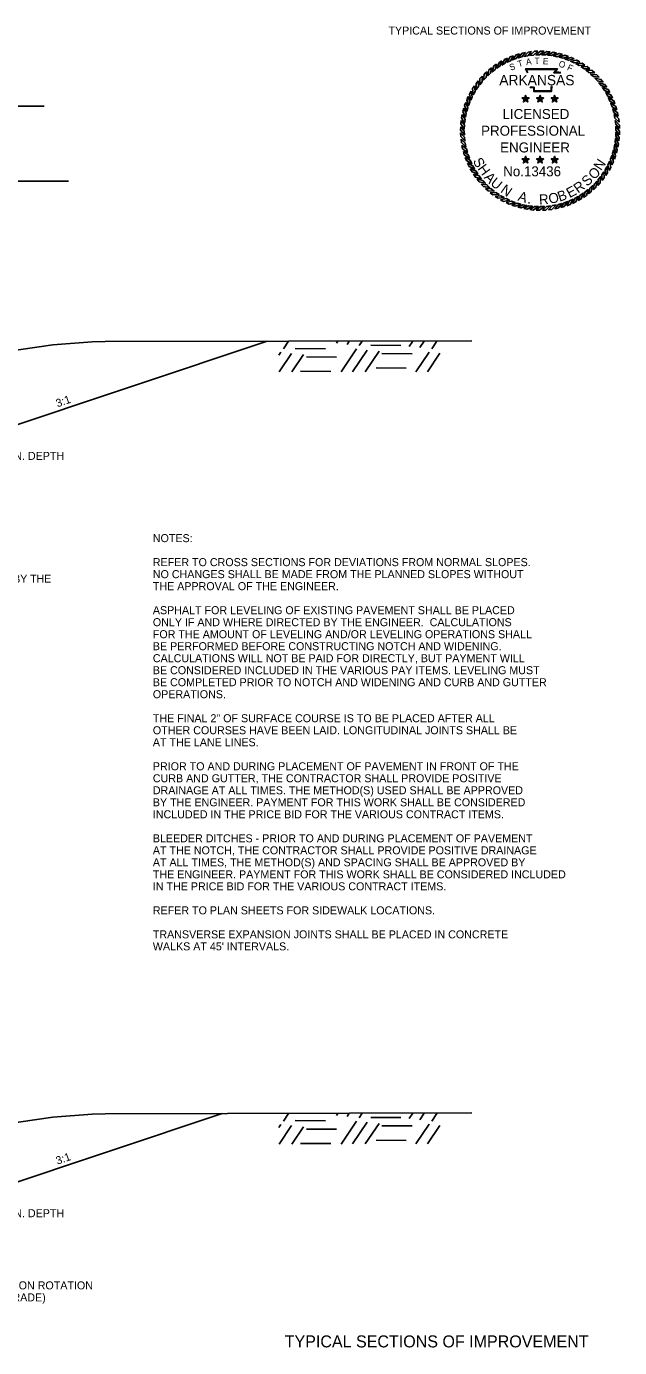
# Model space of a CAD drawing. Extents: x 1001270 to 1003428, y 1840152 to 1842912.
# Drawn here: x 1001384 to 1001428.5, y 1842241.3 to 1842340.4 of the extents above; entities that cross this region are included whole.
import ezdxf

# ---------------------------------------------------------------- set-up
doc = ezdxf.new("R2010")
doc.units = 0
for name, color, linetype in [('1', 7, 'Continuous'), ('19', 7, 'Continuous'), ('60', 7, 'Continuous'), ('Default', 7, 'Continuous'), ('G-ANNO-SYMB', 7, 'Continuous')]:
    doc.layers.add(name, color=color, linetype=linetype)

msp = doc.modelspace()

# ---------------------------------------------------------------- linework, layer by layer
at = {"layer": '19'}
for p, q in [((1001364.368, 1842334.379), (1001385.294, 1842334.379)), ((1001364.368, 1842328.779), (1001387.13, 1842328.779)), ((1001379.87, 1842309.383), (1001402.036, 1842316.771)), ((1001403.257, 1842316.192), (1001403.648, 1842316.775)), ((1001407.242, 1842316.626), (1001407.348, 1842316.776)), ((1001408.037, 1842316.534), (1001408.203, 1842316.779)), ((1001408.932, 1842316.442), (1001409.158, 1842316.781)), ((1001412.696, 1842316.387), (1001412.958, 1842316.782)), ((1001413.491, 1842316.295), (1001413.823, 1842316.783)), ((1001414.386, 1842316.203), (1001414.767, 1842316.777)), ((1001402.917, 1842315.724), (1001403.071, 1842315.95)), ((1001402.939, 1842314.475), (1001403.866, 1842315.858)), ((1001403.894, 1842314.478), (1001404.761, 1842315.766)), ((1001404.145, 1842316.231), (1001406.405, 1842316.21)), ((1001407.594, 1842314.479), (1001408.746, 1842316.2)), ((1001408.449, 1842314.481), (1001409.541, 1842316.108)), ((1001409.404, 1842314.484), (1001410.436, 1842316.016)), ((1001409.82, 1842316.471), (1001412.08, 1842316.46)), ((1001410.65, 1842315.843), (1001412.92, 1842315.831)), ((1001413.204, 1842314.485), (1001414.2, 1842315.96)), ((1001414.059, 1842314.487), (1001414.995, 1842315.869)), ((1001404.985, 1842315.602), (1001407.245, 1842315.58)), ((1001410.208, 1842314.773), (1001412.467, 1842314.751)), ((1001404.532, 1842314.523), (1001406.803, 1842314.51)), ((1001379.87, 1842252.613), (1001398.674, 1842258.881)), ((1001403.257, 1842258.309), (1001403.648, 1842258.892)), ((1001404.145, 1842258.348), (1001406.405, 1842258.327)), ((1001407.242, 1842258.743), (1001407.348, 1842258.893)), ((1001407.594, 1842256.596), (1001408.746, 1842258.317)), ((1001408.037, 1842258.651), (1001408.203, 1842258.896)), ((1001408.449, 1842256.598), (1001409.541, 1842258.225)), ((1001408.932, 1842258.559), (1001409.158, 1842258.898)), ((1001409.82, 1842258.589), (1001412.08, 1842258.577)), ((1001412.696, 1842258.504), (1001412.958, 1842258.899)), ((1001413.491, 1842258.412), (1001413.823, 1842258.9)), ((1001414.386, 1842258.32), (1001414.767, 1842258.894)), ((1001402.917, 1842257.841), (1001403.071, 1842258.067)), ((1001402.939, 1842256.592), (1001403.866, 1842257.975)), ((1001403.894, 1842256.595), (1001404.761, 1842257.883)), ((1001404.985, 1842257.719), (1001407.245, 1842257.697)), ((1001409.404, 1842256.601), (1001410.436, 1842258.133)), ((1001410.65, 1842257.96), (1001412.92, 1842257.948)), ((1001413.204, 1842256.602), (1001414.2, 1842258.077)), ((1001414.059, 1842256.604), (1001414.995, 1842257.986)), ((1001404.532, 1842256.64), (1001406.803, 1842256.627)), ((1001410.208, 1842256.89), (1001412.467, 1842256.868))]:
    msp.add_line(p, q, dxfattribs=at)
for points in [[(1001308.144, 1842305.359), (1001317.69, 1842306.018), (1001325.322, 1842307.545), (1001329.477, 1842307.756), (1001334.361, 1842308.581), (1001340.15, 1842308.799), (1001346.517, 1842309.325), (1001351.216, 1842309.645), (1001358.361, 1842310.429), (1001362.7, 1842310.493), (1001370.347, 1842310.619), (1001372.903, 1842311.251), (1001376.995, 1842314.166), (1001381.307, 1842315.815), (1001385.954, 1842316.502), (1001388.908, 1842316.716)], [(1001388.908, 1842316.716), (1001389.885, 1842316.745), (1001417.402, 1842316.805)], [(1001308.144, 1842247.476), (1001317.69, 1842248.135), (1001325.322, 1842249.662), (1001329.477, 1842249.873), (1001334.361, 1842250.698), (1001340.15, 1842250.916), (1001346.517, 1842251.442), (1001351.216, 1842251.762), (1001358.361, 1842252.546), (1001362.7, 1842252.61), (1001370.347, 1842252.736), (1001372.903, 1842253.368), (1001376.995, 1842256.283), (1001381.307, 1842257.932), (1001385.954, 1842258.619), (1001388.908, 1842258.834)], [(1001388.908, 1842258.834), (1001389.885, 1842258.862), (1001417.402, 1842258.922)]]:
    msp.add_lwpolyline(points, dxfattribs=at)
at = {"layer": 'G-ANNO-SYMB'}
for points in [[(1001421.88, 1842338.481), (1001421.625, 1842338.448), (1001421.314, 1842338.114), (1001421.586, 1842338.166)], [(1001422.347, 1842338.513), (1001422.091, 1842338.5), (1001421.754, 1842338.191), (1001422.029, 1842338.221)], [(1001422.816, 1842338.508), (1001422.559, 1842338.515), (1001422.199, 1842338.233), (1001422.476, 1842338.242)], [(1001423.282, 1842338.466), (1001423.027, 1842338.493), (1001422.646, 1842338.241), (1001422.923, 1842338.228)], [(1001423.744, 1842338.388), (1001423.492, 1842338.435), (1001423.092, 1842338.213), (1001423.367, 1842338.179)], [(1001419.256, 1842337.545), (1001419.045, 1842337.4), (1001418.919, 1842336.96), (1001419.138, 1842337.13)], [(1001419.658, 1842337.785), (1001419.436, 1842337.657), (1001419.276, 1842337.229), (1001419.507, 1842337.381)], [(1001420.078, 1842337.993), (1001419.846, 1842337.884), (1001419.653, 1842337.469), (1001419.896, 1842337.603)], [(1001420.513, 1842338.168), (1001420.273, 1842338.077), (1001420.048, 1842337.679), (1001420.3, 1842337.793)], [(1001420.96, 1842338.308), (1001420.714, 1842338.236), (1001420.458, 1842337.857), (1001420.719, 1842337.951)], [(1001421.416, 1842338.413), (1001421.165, 1842338.36), (1001420.881, 1842338.002), (1001421.148, 1842338.075)], [(1001424.198, 1842338.273), (1001423.951, 1842338.34), (1001423.535, 1842338.151), (1001423.806, 1842338.095)], [(1001424.642, 1842338.124), (1001424.401, 1842338.21), (1001423.971, 1842338.054), (1001424.237, 1842337.976)], [(1001425.073, 1842337.94), (1001424.839, 1842338.045), (1001424.398, 1842337.923), (1001424.658, 1842337.825)], [(1001425.488, 1842337.723), (1001425.263, 1842337.846), (1001424.814, 1842337.759), (1001425.065, 1842337.641)], [(1001425.885, 1842337.474), (1001425.67, 1842337.614), (1001425.216, 1842337.562), (1001425.457, 1842337.425)], [(1001418.18, 1842336.645), (1001418.008, 1842336.455), (1001417.988, 1842335.998), (1001418.161, 1842336.215)], [(1001418.515, 1842336.973), (1001418.329, 1842336.797), (1001418.273, 1842336.343), (1001418.462, 1842336.545)], [(1001418.874, 1842337.273), (1001418.675, 1842337.112), (1001418.584, 1842336.664), (1001418.789, 1842336.851)], [(1001426.261, 1842337.195), (1001426.058, 1842337.351), (1001425.601, 1842337.335), (1001425.83, 1842337.179)], [(1001426.614, 1842336.887), (1001426.424, 1842337.059), (1001425.967, 1842337.079), (1001426.183, 1842336.905)], [(1001426.942, 1842336.552), (1001426.765, 1842336.738), (1001426.312, 1842336.794), (1001426.514, 1842336.604)], [(1001427.242, 1842336.192), (1001427.081, 1842336.392), (1001426.633, 1842336.483), (1001426.82, 1842336.278)], [(1001417.344, 1842335.52), (1001417.221, 1842335.294), (1001417.308, 1842334.846), (1001417.426, 1842335.096)], [(1001417.593, 1842335.916), (1001417.453, 1842335.702), (1001417.504, 1842335.247), (1001417.642, 1842335.488)], [(1001417.872, 1842336.292), (1001417.716, 1842336.089), (1001417.732, 1842335.632), (1001417.887, 1842335.862)], [(1001427.513, 1842335.81), (1001427.368, 1842336.022), (1001426.929, 1842336.148), (1001427.099, 1842335.929)], [(1001427.754, 1842335.408), (1001427.626, 1842335.631), (1001427.198, 1842335.791), (1001427.35, 1842335.559)], [(1001416.943, 1842334.674), (1001416.857, 1842334.432), (1001417.013, 1842334.002), (1001417.09, 1842334.269)], [(1001417.127, 1842335.105), (1001417.022, 1842334.87), (1001417.144, 1842334.43), (1001417.242, 1842334.689)], [(1001421.427, 1842334.925), (1001421.366, 1842335.009), (1001421.167, 1842335.009), (1001421.328, 1842334.893)], [(1001421.427, 1842334.925), (1001421.328, 1842334.893), (1001421.266, 1842334.704), (1001421.427, 1842334.821)], [(1001421.427, 1842334.925), (1001421.488, 1842335.009), (1001421.427, 1842335.197), (1001421.366, 1842335.009)], [(1001421.427, 1842334.925), (1001421.526, 1842334.893), (1001421.686, 1842335.009), (1001421.488, 1842335.009)], [(1001421.427, 1842334.925), (1001421.427, 1842334.821), (1001421.587, 1842334.704), (1001421.526, 1842334.893)], [(1001422.518, 1842334.925), (1001422.456, 1842335.009), (1001422.258, 1842335.009), (1001422.419, 1842334.893)], [(1001422.518, 1842334.925), (1001422.419, 1842334.893), (1001422.357, 1842334.704), (1001422.518, 1842334.821)], [(1001422.518, 1842334.925), (1001422.579, 1842335.009), (1001422.518, 1842335.197), (1001422.456, 1842335.009)], [(1001422.518, 1842334.925), (1001422.617, 1842334.893), (1001422.777, 1842335.009), (1001422.579, 1842335.009)], [(1001422.518, 1842334.925), (1001422.518, 1842334.821), (1001422.678, 1842334.704), (1001422.617, 1842334.893)], [(1001423.609, 1842334.925), (1001423.547, 1842335.009), (1001423.349, 1842335.009), (1001423.51, 1842334.893)], [(1001423.609, 1842334.925), (1001423.51, 1842334.893), (1001423.448, 1842334.704), (1001423.609, 1842334.821)], [(1001423.609, 1842334.925), (1001423.67, 1842335.009), (1001423.609, 1842335.197), (1001423.547, 1842335.009)], [(1001423.609, 1842334.925), (1001423.708, 1842334.893), (1001423.868, 1842335.009), (1001423.67, 1842335.009)], [(1001423.609, 1842334.925), (1001423.609, 1842334.821), (1001423.769, 1842334.704), (1001423.708, 1842334.893)], [(1001427.962, 1842334.989), (1001427.852, 1842335.221), (1001427.438, 1842335.414), (1001427.571, 1842335.171)], [(1001428.137, 1842334.554), (1001428.045, 1842334.794), (1001427.647, 1842335.019), (1001427.761, 1842334.766)], [(1001428.277, 1842334.107), (1001428.204, 1842334.353), (1001427.825, 1842334.609), (1001427.919, 1842334.348)], [(1001416.679, 1842333.775), (1001416.632, 1842333.523), (1001416.854, 1842333.123), (1001416.888, 1842333.398)], [(1001416.793, 1842334.23), (1001416.726, 1842333.982), (1001416.916, 1842333.566), (1001416.972, 1842333.837)], [(1001428.381, 1842333.65), (1001428.328, 1842333.901), (1001427.97, 1842334.186), (1001428.044, 1842333.919)], [(1001428.449, 1842333.187), (1001428.417, 1842333.441), (1001428.082, 1842333.753), (1001428.134, 1842333.481)], [(1001416.559, 1842332.847), (1001416.552, 1842332.591), (1001416.833, 1842332.23), (1001416.825, 1842332.507)], [(1001416.601, 1842333.314), (1001416.574, 1842333.059), (1001416.826, 1842332.677), (1001416.839, 1842332.954)], [(1001428.481, 1842332.72), (1001428.468, 1842332.976), (1001428.159, 1842333.313), (1001428.19, 1842333.037)], [(1001428.476, 1842332.251), (1001428.483, 1842332.508), (1001428.202, 1842332.868), (1001428.211, 1842332.591)], [(1001416.554, 1842332.379), (1001416.567, 1842332.122), (1001416.876, 1842331.785), (1001416.845, 1842332.061)], [(1001416.586, 1842331.911), (1001416.619, 1842331.657), (1001416.953, 1842331.345), (1001416.901, 1842331.617)], [(1001428.242, 1842330.868), (1001428.309, 1842331.116), (1001428.119, 1842331.532), (1001428.063, 1842331.261)], [(1001428.356, 1842331.323), (1001428.404, 1842331.575), (1001428.182, 1842331.975), (1001428.147, 1842331.7)], [(1001428.434, 1842331.785), (1001428.462, 1842332.04), (1001428.209, 1842332.421), (1001428.196, 1842332.144)], [(1001416.654, 1842331.448), (1001416.707, 1842331.197), (1001417.065, 1842330.912), (1001416.992, 1842331.179)], [(1001416.759, 1842330.991), (1001416.831, 1842330.745), (1001417.21, 1842330.489), (1001417.116, 1842330.75)], [(1001416.899, 1842330.544), (1001416.99, 1842330.304), (1001417.388, 1842330.079), (1001417.274, 1842330.332)], [(1001421.427, 1842330.357), (1001421.488, 1842330.441), (1001421.427, 1842330.629), (1001421.366, 1842330.441)], [(1001422.518, 1842330.357), (1001422.579, 1842330.441), (1001422.518, 1842330.629), (1001422.456, 1842330.441)], [(1001423.609, 1842330.357), (1001423.67, 1842330.441), (1001423.609, 1842330.629), (1001423.547, 1842330.441)], [(1001427.909, 1842329.994), (1001428.013, 1842330.228), (1001427.891, 1842330.668), (1001427.793, 1842330.409)], [(1001428.092, 1842330.425), (1001428.179, 1842330.666), (1001428.022, 1842331.096), (1001427.945, 1842330.83)], [(1001417.073, 1842330.109), (1001417.183, 1842329.878), (1001417.598, 1842329.684), (1001417.464, 1842329.927)], [(1001417.282, 1842329.69), (1001417.409, 1842329.467), (1001417.838, 1842329.307), (1001417.685, 1842329.539)], [(1001421.427, 1842330.357), (1001421.366, 1842330.441), (1001421.167, 1842330.441), (1001421.328, 1842330.324)], [(1001421.427, 1842330.357), (1001421.328, 1842330.324), (1001421.266, 1842330.136), (1001421.427, 1842330.252)], [(1001421.427, 1842330.357), (1001421.526, 1842330.324), (1001421.686, 1842330.441), (1001421.488, 1842330.441)], [(1001421.427, 1842330.357), (1001421.427, 1842330.252), (1001421.587, 1842330.136), (1001421.526, 1842330.324)], [(1001422.518, 1842330.357), (1001422.456, 1842330.441), (1001422.258, 1842330.441), (1001422.419, 1842330.324)], [(1001422.518, 1842330.357), (1001422.419, 1842330.324), (1001422.357, 1842330.136), (1001422.518, 1842330.252)], [(1001422.518, 1842330.357), (1001422.617, 1842330.324), (1001422.777, 1842330.441), (1001422.579, 1842330.441)], [(1001422.518, 1842330.357), (1001422.518, 1842330.252), (1001422.678, 1842330.136), (1001422.617, 1842330.324)], [(1001423.609, 1842330.357), (1001423.547, 1842330.441), (1001423.349, 1842330.441), (1001423.51, 1842330.324)], [(1001423.609, 1842330.357), (1001423.51, 1842330.324), (1001423.448, 1842330.136), (1001423.609, 1842330.252)], [(1001423.609, 1842330.357), (1001423.708, 1842330.324), (1001423.868, 1842330.441), (1001423.67, 1842330.441)], [(1001423.609, 1842330.357), (1001423.609, 1842330.252), (1001423.769, 1842330.136), (1001423.708, 1842330.324)], [(1001427.442, 1842329.182), (1001427.583, 1842329.397), (1001427.531, 1842329.851), (1001427.394, 1842329.61)], [(1001427.691, 1842329.579), (1001427.814, 1842329.804), (1001427.727, 1842330.253), (1001427.609, 1842330.002)], [(1001417.522, 1842329.288), (1001417.667, 1842329.076), (1001418.106, 1842328.95), (1001417.936, 1842329.169)], [(1001417.793, 1842328.906), (1001417.954, 1842328.706), (1001418.402, 1842328.615), (1001418.216, 1842328.82)], [(1001418.094, 1842328.546), (1001418.27, 1842328.36), (1001418.724, 1842328.304), (1001418.522, 1842328.494)], [(1001426.52, 1842328.125), (1001426.707, 1842328.301), (1001426.763, 1842328.755), (1001426.573, 1842328.553)], [(1001426.855, 1842328.453), (1001427.027, 1842328.643), (1001427.047, 1842329.1), (1001426.874, 1842328.884)], [(1001427.163, 1842328.806), (1001427.32, 1842329.009), (1001427.304, 1842329.466), (1001427.148, 1842329.237)], [(1001418.421, 1842328.212), (1001418.612, 1842328.04), (1001419.069, 1842328.02), (1001418.852, 1842328.193)], [(1001418.774, 1842327.904), (1001418.978, 1842327.747), (1001419.435, 1842327.763), (1001419.205, 1842327.919)], [(1001419.15, 1842327.624), (1001419.365, 1842327.484), (1001419.82, 1842327.536), (1001419.579, 1842327.673)], [(1001424.957, 1842327.105), (1001425.189, 1842327.215), (1001425.382, 1842327.629), (1001425.14, 1842327.496)], [(1001425.377, 1842327.313), (1001425.599, 1842327.441), (1001425.76, 1842327.869), (1001425.528, 1842327.717)], [(1001425.779, 1842327.553), (1001425.991, 1842327.698), (1001426.117, 1842328.138), (1001425.898, 1842327.968)], [(1001426.161, 1842327.825), (1001426.361, 1842327.986), (1001426.452, 1842328.434), (1001426.247, 1842328.247)], [(1001419.547, 1842327.375), (1001419.772, 1842327.252), (1001420.221, 1842327.34), (1001419.97, 1842327.458)], [(1001419.962, 1842327.158), (1001420.196, 1842327.053), (1001420.637, 1842327.175), (1001420.378, 1842327.273)], [(1001420.393, 1842326.974), (1001420.635, 1842326.888), (1001421.064, 1842327.045), (1001420.798, 1842327.122)], [(1001420.837, 1842326.825), (1001421.085, 1842326.758), (1001421.501, 1842326.947), (1001421.229, 1842327.004)], [(1001421.291, 1842326.711), (1001421.543, 1842326.663), (1001421.943, 1842326.885), (1001421.668, 1842326.92)], [(1001421.753, 1842326.632), (1001422.008, 1842326.605), (1001422.39, 1842326.857), (1001422.113, 1842326.87)], [(1001422.22, 1842326.591), (1001422.476, 1842326.583), (1001422.837, 1842326.865), (1001422.56, 1842326.856)], [(1001422.688, 1842326.586), (1001422.944, 1842326.598), (1001423.282, 1842326.907), (1001423.006, 1842326.877)], [(1001423.156, 1842326.617), (1001423.41, 1842326.65), (1001423.722, 1842326.985), (1001423.45, 1842326.933)], [(1001423.619, 1842326.686), (1001423.87, 1842326.738), (1001424.155, 1842327.096), (1001423.887, 1842327.023)], [(1001424.076, 1842326.79), (1001424.322, 1842326.862), (1001424.577, 1842327.242), (1001424.317, 1842327.148)], [(1001424.523, 1842326.93), (1001424.762, 1842327.022), (1001424.988, 1842327.42), (1001424.735, 1842327.305)]]:
    msp.add_lwpolyline(points, close=True, dxfattribs=at)
for points in [[(1001421.562, 1842336.879), (1001421.423, 1842337.18), (1001423.829, 1842337.182), (1001423.628, 1842336.929), (1001423.792, 1842336.931), (1001423.928, 1842336.933), (1001424.065, 1842336.918)], [(1001421.596, 1842336.895), (1001421.482, 1842337.142), (1001423.75, 1842337.144), (1001423.548, 1842336.89), (1001423.792, 1842336.893), (1001423.926, 1842336.895), (1001424.06, 1842336.88)], [(1001423.45, 1842335.871), (1001423.409, 1842335.837), (1001423.395, 1842335.787), (1001423.382, 1842335.663), (1001423.382, 1842335.496), (1001422.038, 1842335.496), (1001422.038, 1842335.721), (1001422.038, 1842335.771), (1001421.984, 1842335.787), (1001421.793, 1842335.787), (1001421.759, 1842335.839)], [(1001423.426, 1842335.9), (1001423.375, 1842335.859), (1001423.358, 1842335.795), (1001423.344, 1842335.665), (1001423.344, 1842335.534), (1001422.077, 1842335.534), (1001422.077, 1842335.721), (1001422.077, 1842335.799), (1001421.99, 1842335.825), (1001421.813, 1842335.825), (1001421.791, 1842335.86)]]:
    msp.add_lwpolyline(points, dxfattribs=at)

# ---------------------------------------------------------------- texts
at = {"layer": '1'}
msp.add_text('TYPICAL SECTIONS OF IMPROVEMENT', height=0.6, dxfattribs=at).set_placement((1001411.138, 1842339.757))
at = {"layer": '19'}
for s, rotation, p in [('3:1', 19.50574, (1001386.305, 1842311.807)), ('3:1', 19.50574, (1001386.305, 1842255.038)), ("(0.36' BELOW PROFILE GRADE)", 359.99538, (1001373.319, 1842244.8)), ('POINT OF SUPERELEVATION ROTATION', 359.99538, (1001373.319, 1842245.7))]:
    msp.add_text(s, height=0.6, rotation=rotation, dxfattribs=at).set_placement(p)
for s, p in [('24" MIN. DEPTH', (1001380.77, 1842307.877)), ('NOTES:', (1001393.46, 1842301.71)), ('REFER TO CROSS SECTIONS FOR DEVIATIONS FROM NORMAL SLOPES.', (1001393.46, 1842299.91)), ('NO CHANGES SHALL BE MADE FROM THE PLANNED SLOPES WITHOUT', (1001393.46, 1842299.01)), ('THE APPROVAL OF THE ENGINEER.', (1001393.46, 1842298.11)), ('ASPHALT FOR LEVELING OF EXISTING PAVEMENT SHALL BE PLACED', (1001393.46, 1842296.31)), ('ONLY IF AND WHERE DIRECTED BY THE ENGINEER.  CALCULATIONS', (1001393.46, 1842295.41)), ('FOR THE AMOUNT OF LEVELING AND/OR LEVELING OPERATIONS SHALL', (1001393.46, 1842294.51)), ('BE PERFORMED BEFORE CONSTRUCTING NOTCH AND WIDENING.', (1001393.46, 1842293.61)), ('CALCULATIONS WILL NOT BE PAID FOR DIRECTLY, BUT PAYMENT WILL', (1001393.46, 1842292.71)), ('BE CONSIDERED INCLUDED IN THE VARIOUS PAY ITEMS. LEVELING MUST ', (1001393.46, 1842291.81)), ('BE COMPLETED PRIOR TO NOTCH AND WIDENING AND CURB AND GUTTER', (1001393.46, 1842290.91)), ('OPERATIONS. ', (1001393.46, 1842290.01)), ('THE FINAL 2" OF SURFACE COURSE IS TO BE PLACED AFTER ALL', (1001393.46, 1842288.21)), ('OTHER COURSES HAVE BEEN LAID. LONGITUDINAL JOINTS SHALL BE', (1001393.46, 1842287.31)), ('AT THE LANE LINES.', (1001393.46, 1842286.41)), ('PRIOR TO AND DURING PLACEMENT OF PAVEMENT IN FRONT OF THE', (1001393.46, 1842284.61)), ('CURB AND GUTTER, THE CONTRACTOR SHALL PROVIDE POSITIVE', (1001393.46, 1842283.71)), ('DRAINAGE AT ALL TIMES. THE METHOD(S) USED SHALL BE APPROVED', (1001393.46, 1842282.81)), ('BY THE ENGINEER. PAYMENT FOR THIS WORK SHALL BE CONSIDERED', (1001393.46, 1842281.91)), ('INCLUDED IN THE PRICE BID FOR THE VARIOUS CONTRACT ITEMS.', (1001393.46, 1842281.01)), ('BLEEDER DITCHES - PRIOR TO AND DURING PLACEMENT OF PAVEMENT', (1001393.46, 1842279.21)), ('AT THE NOTCH, THE CONTRACTOR SHALL PROVIDE POSITIVE DRAINAGE', (1001393.46, 1842278.31)), ('AT ALL TIMES, THE METHOD(S) AND SPACING SHALL BE APPROVED BY', (1001393.46, 1842277.41)), ('THE ENGINEER. PAYMENT FOR THIS WORK SHALL BE CONSIDERED INCLUDED', (1001393.46, 1842276.51)), ('IN THE PRICE BID FOR THE VARIOUS CONTRACT ITEMS.', (1001393.46, 1842275.61)), ('REFER TO PLAN SHEETS FOR SIDEWALK LOCATIONS.', (1001393.46, 1842273.81)), ('TRANSVERSE EXPANSION JOINTS SHALL BE PLACED IN CONCRETE', (1001393.46, 1842272.01)), ("WALKS AT 45' INTERVALS.", (1001393.46, 1842271.11)), ('24" MIN. DEPTH', (1001380.77, 1842251.108))]:
    msp.add_text(s, height=0.6, dxfattribs=at).set_placement(p)
at = {"layer": '60'}
msp.add_text('TYPICAL SECTIONS OF IMPROVEMENT', height=0.9, dxfattribs=at).set_placement((1001403.354, 1842241.35))
at = {"layer": 'Default'}
msp.add_text('TO BE USED IF AND WHERE DIRECTED BY THE ', height=0.59001, rotation=359.99538, dxfattribs=at).set_placement((1001367.771, 1842298.671))
at = {"layer": 'G-ANNO-SYMB'}
for s, height, rotation, p in [('S', 0.475, 19.77256, (1001420.309, 1842337.037)), ('T', 0.475, 16.90148, (1001420.912, 1842337.308)), ('A', 0.475, 8.67877, (1001421.489, 1842337.458)), ('T', 0.475, 1.47887, (1001422.102, 1842337.553)), ('E', 0.475, 356.67203, (1001422.709, 1842337.538)), ('O', 0.475, 341.2218, (1001423.862, 1842337.376)), ('F', 0.475, 335.36282, (1001424.501, 1842337.125)), ('ARKANSAS', 0.7747, 360, (1001419.456, 1842335.957)), ('LICENSED', 0.75, 360, (1001419.696, 1842333.428)), ('PROFESSIONAL', 0.75, 360, (1001418.089, 1842332.174)), ('ENGINEER', 0.75, 360, (1001419.518, 1842330.92)), ('S', 0.75, 298.16364, (1001417.45, 1842330.289)), ('H', 0.75, 305.61905, (1001417.792, 1842329.702)), ('No.13436', 0.747, 360, (1001419.754, 1842329.132)), ('O', 0.75, 44.77573, (1001426.571, 1842328.83)), ('N', 0.75, 56.10067, (1001427.092, 1842329.506)), ('A', 0.75, 313.44722, (1001418.268, 1842329.017)), ('U', 0.75, 320.90262, (1001418.735, 1842328.528)), ('N', 0.75, 324.93262, (1001419.491, 1842327.969)), ('R', 0.75, 35.65967, (1001425.366, 1842327.823)), ('S', 0.75, 43.48784, (1001426.055, 1842328.333)), ('A', 0.75, 343.09908, (1001420.799, 1842327.326)), ('R', 0.75, 3.22866, (1001422.455, 1842327.012)), ('O', 0.75, 11.42961, (1001423.223, 1842327.061)), ('B', 0.75, 18.88501, (1001423.974, 1842327.22)), ('E', 0.75, 27.83149, (1001424.732, 1842327.491)), ('.', 0.75, 351.30002, (1001421.536, 1842327.107))]:
    msp.add_text(s, height=height, rotation=rotation, dxfattribs=at).set_placement(p)

doc.saveas('drawing.dxf')
